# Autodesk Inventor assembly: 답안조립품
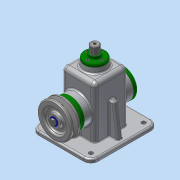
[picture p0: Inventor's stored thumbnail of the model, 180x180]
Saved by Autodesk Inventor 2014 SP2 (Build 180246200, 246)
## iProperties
Created: 2016-08
Part Number: 답안조립품
Document SubType Name: Assembly
Designer: user
Author: user
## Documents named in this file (19)
- C:\Users\user\Desktop\460820V1023\답안조립품.iam
- C:\Users\user\Desktop\460820V1023\본체.ipt
- C:\Users\user\Desktop\460820V1023\베어링 15 x 35 x 11.ipt
- C:\Users\user\Desktop\460820V1023\상부부시.ipt
- C:\Users\user\Desktop\460820V1023\편심축.ipt
- C:\Users\user\Desktop\460820V1023\링크.ipt
- C:\Users\user\Desktop\460820V1023\고정핀.ipt
- C:\Users\user\Desktop\460820V1023\멈춤링 6 x 5.ipt
- C:\Users\user\Desktop\460820V1023\슬라이드바.ipt
- C:\Users\user\Desktop\460820V1023\멈춤링 15 x 1.ipt
- C:\Users\user\Desktop\460820V1023\와셔.ipt
- C:\Users\user\Desktop\460820V1023\뒤커버.ipt
- C:\Users\user\Desktop\460820V1023\앞커버.ipt
- C:\Users\user\Desktop\460820V1023\오일실 15 25 7.ipt
- C:\Users\user\Desktop\460820V1023\볼트 M3 x 8.ipt
- C:\Users\user\Desktop\460820V1023\볼트 M4 x 10.ipt
- C:\Users\user\Desktop\460820V1023\V-벨트풀리.ipt
- C:\Users\user\Desktop\460820V1023\키 5 x 5 x 14.ipt
- C:\Users\user\Desktop\460820V1023\볼트 M6 x 12.ipt
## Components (15 placed, 5 different names)
1. 고정핀:1 — 강체:1, 강체:2
2. V-벨트풀리:1 — 각도:1
3. ISO 4018 M6 x 12:1 — 강체:9
4. ISO 4762 M3 x 8:1 — 강체:5
5. ISO 4762 M3 x 8:2
6. ISO 4762 M3 x 8:3
7. ISO 4762 M3 x 8:4
8. ISO 4762 M4 x 10:2 — 강체:7
9. ISO 4762 M4 x 10:1 — 강체:6
10. ISO 4762 M4 x 10:3
11. ISO 4762 M4 x 10:4
12. ISO 4762 M4 x 10:5
13. ISO 4762 M4 x 10:6
14. ISO 4762 M4 x 10:7
15. ISO 4762 M4 x 10:8
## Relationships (7: WeldJoint 6, Angle 1)
- 강체:1 [WeldJoint]: 고정핀:1
- 강체:2 [WeldJoint]: 고정핀:1
- 강체:5 [WeldJoint]: ISO 4762 M3 x 8:1
- 강체:6 [WeldJoint]: ISO 4762 M4 x 10:1
- 강체:7 [WeldJoint]: ISO 4762 M4 x 10:2
- 각도:1 [Angle]: V-벨트풀리:1
- 강체:9 [WeldJoint]: ISO 4018 M6 x 12:1
